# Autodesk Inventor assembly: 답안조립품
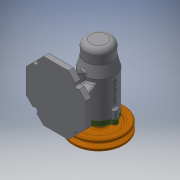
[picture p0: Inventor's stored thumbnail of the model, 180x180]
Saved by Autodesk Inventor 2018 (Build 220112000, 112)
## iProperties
Created: 2019-12
Part Number: 답안조립품
Document SubType Name: Assembly
Designer: Administrator
Author: Administrator
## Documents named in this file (12)
- C:\Users\Administrator\Desktop\491204V1067\답안조립품.iam
- C:\Users\Administrator\Desktop\491204V1067\본체.ipt
- C:\Users\Administrator\Desktop\491204V1067\축.ipt
- C:\Users\Administrator\Desktop\491204V1067\베어링 6004.ipt
- C:\Users\Administrator\Desktop\491204V1067\베어링 51202.ipt
- C:\Users\Administrator\Desktop\491204V1067\Ű 5 x 5 x 16.ipt
- C:\Users\Administrator\Desktop\491204V1067\어댑터슬리브.ipt
- C:\Users\Administrator\Desktop\491204V1067\오일 실.ipt
- C:\Users\Administrator\Desktop\491204V1067\V벨트풀리.ipt
- C:\Users\Administrator\Desktop\491204V1067\멈춤나사 M3.ipt
- C:\Users\Administrator\Desktop\491204V1067\커버.ipt
- C:\Users\Administrator\Desktop\491204V1067\볼트 M4.ipt
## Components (2 placed, 2 different names)
1. Ű 5 x 5 x 16:1 — 각도:1
2. V벨트풀리:1
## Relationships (1: Angle 1)
- 각도:1 [Angle]: Ű 5 x 5 x 16:1
